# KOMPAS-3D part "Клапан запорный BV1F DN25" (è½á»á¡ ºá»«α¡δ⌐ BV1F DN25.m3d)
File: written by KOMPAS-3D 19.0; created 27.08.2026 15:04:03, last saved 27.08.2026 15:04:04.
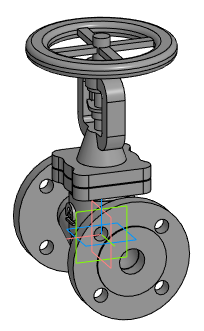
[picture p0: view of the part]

Document properties: Автор: Энергия; Полное имя файла: E:\Dendor\_3D для проектировщиков\5.6 Клапан запорный BV1F\stp\Клапан запорный BV1F DN25.m3d

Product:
- Part/product: Клапан запорный BV1F DN25
    Масса: 6.58763

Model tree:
1. Операция без истории:1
